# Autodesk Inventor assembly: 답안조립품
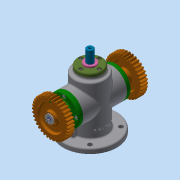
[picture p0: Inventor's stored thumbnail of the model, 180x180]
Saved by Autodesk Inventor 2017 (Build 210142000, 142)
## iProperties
Part Number: 답안조립품
Material: 일반
Document SubType Name: Assembly
Designer: mrc
Mass: 1861.33 g
Surface Area: 1735.34 cm^2
Volume: 520.939 cm^3
Density: 3.57302 g/cm^3
Author: mrc
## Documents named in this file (17)
- C:\Users\mrc\Desktop\600606V1010\답안조립품.iam
- C:\Users\mrc\Desktop\600606V1010\본체.ipt
- C:\Users\mrc\Desktop\600606V1010\Ű 4x4x12.ipt
- C:\Users\mrc\Desktop\600606V1010\가변스프링.ipt
- C:\Users\mrc\Desktop\600606V1010\멈춤링.ipt
- C:\Users\mrc\Desktop\600606V1010\베어링 6203.ipt
- C:\Users\mrc\Desktop\600606V1010\볼트 M4.ipt
- C:\Users\mrc\Desktop\600606V1010\부시.ipt
- C:\Users\mrc\Desktop\600606V1010\스퍼기어.ipt
- C:\Users\mrc\Desktop\600606V1010\스프링와셔.ipt
- C:\Users\mrc\Desktop\600606V1010\스프링조립용 와셔.ipt
- C:\Users\mrc\Desktop\600606V1010\슬라이더.ipt
- C:\Users\mrc\Desktop\600606V1010\오일 실 17 30 8.ipt
- C:\Users\mrc\Desktop\600606V1010\커버 A.ipt
- C:\Users\mrc\Desktop\600606V1010\커버 B.ipt
- C:\Users\mrc\Desktop\600606V1010\편심축.ipt
- C:\Users\mrc\Desktop\600606V1010\평와셔.ipt
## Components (3 placed, 2 different names)
1. Ű 4x4x12:1
2. 가변스프링:1
3. Ű 4x4x12:2
